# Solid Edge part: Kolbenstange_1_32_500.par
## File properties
Username: ahadarics
Dokumentum tartalom típus: 0
Author: ahadarics
Last saved by: ahadarics
Revision: 91
Sűrűség: 0,000 kg/m^3
Pontosság: 0,990
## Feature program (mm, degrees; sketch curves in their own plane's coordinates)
base feature "unnamed BaseFeature 1"
thread "unnamed Thread 1"
chamfer "Letörés_1"  SetBackValue2 = 20 deg
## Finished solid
Body 1: solid body, 19 faces, 27 edges, 11 vertices.
  Faces by surface: plane 8, cylinder 5, cone 3, torus 3
  Edges by curve: circle 15, line 7, curve on surface 3, ellipse 2
Bounding box of the edges (mm; curved faces can reach further): 32.000 x 32.000 x 615.500, from (-16, -16, -50.25) to (16, 16, 565.25).
Cylindrical faces by radius (mm): R3.95 x1, R5 x1, R5.8 x1, R6 x1, R16 x1
Conical faces (half-angle, radius in mm at the cone's reference point): 20 deg R5 x1, 30 deg R5.9 x1, 60 deg R4.475 x1
Toroidal faces (ring radius, tube radius in mm): R4.35 r0.4 x2, R4.6 r1.2 x1
Planar faces by outward normal: +x 1, +z 3, -x 1, -z 1, oblique 2
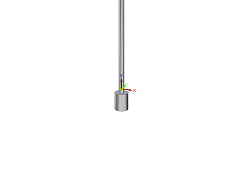
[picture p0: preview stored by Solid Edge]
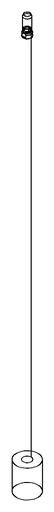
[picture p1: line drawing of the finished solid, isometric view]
